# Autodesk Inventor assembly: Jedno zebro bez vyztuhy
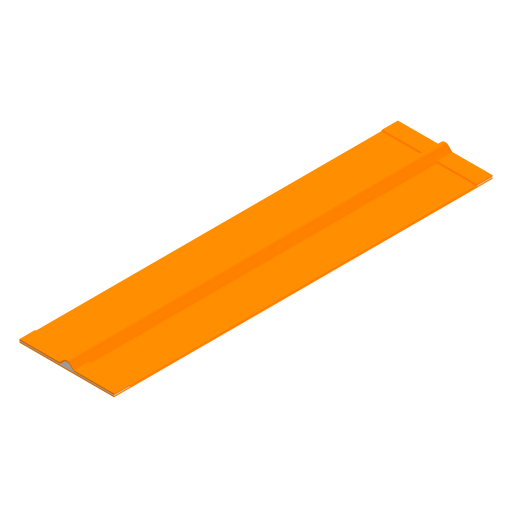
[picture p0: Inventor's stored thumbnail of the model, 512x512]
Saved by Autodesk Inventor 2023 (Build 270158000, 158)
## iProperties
Created: 2025-03
Part Number: Jedno zebro bez vyztuhy
Document SubType Name: Assembly
Designer: tomik
Author: tomik
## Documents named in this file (4)
- C:\Users\tomik\Desktop\Růčka_Tomáš_přílohy\Vyztužení\Jedno žebro\Jedno zebro bez vyztuhy.iam
- C:\Users\tomik\Desktop\Diplomka\Struktury\Desky\Struktury_20.3\Jedno žebro bez výztuhy\Spodni tkanina 50x200.ipt
- C:\Users\tomik\Desktop\Diplomka\Struktury\Desky\Struktury_20.3\Jedno žebro bez výztuhy\Zebro bez vyztuhy.ipt
- C:\Users\tomik\Desktop\Diplomka\Struktury\Desky\Struktury_20.3\Jedno žebro bez výztuhy\Horni tkanina.ipt
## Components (3 placed, 3 different names)
1. Spodni tkanina 50x200:1 — Proti sobě:1, Proti sobě:2, Stejný směr:1, Proti sobě:3, Stejný směr:2, Proti sobě:4, Proti sobě:5
2. Zebro bez vyztuhy:1 — Proti sobě:3, Stejný směr:2, Proti sobě:4, Proti sobě:6, Proti sobě:7
3. Horni tkanina:1 — Proti sobě:5, Proti sobě:6, Proti sobě:7, Stejný směr:3
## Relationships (10: Mate 7, Flush 3)
- Proti sobě:1 [Mate]: Spodni tkanina 50x200:1
- Proti sobě:2 [Mate]: Spodni tkanina 50x200:1
- Stejný směr:1 [Flush]: Spodni tkanina 50x200:1
- Proti sobě:3 [Mate]: Spodni tkanina 50x200:1 ↔ Zebro bez vyztuhy:1
- Stejný směr:2 [Flush]: Spodni tkanina 50x200:1 ↔ Zebro bez vyztuhy:1
- Proti sobě:4 [Mate]: Spodni tkanina 50x200:1 ↔ Zebro bez vyztuhy:1
- Proti sobě:5 [Mate]: Spodni tkanina 50x200:1 ↔ Horni tkanina:1
- Proti sobě:6 [Mate]: Zebro bez vyztuhy:1 ↔ Horni tkanina:1
- Proti sobě:7 [Mate]: Zebro bez vyztuhy:1 ↔ Horni tkanina:1
- Stejný směr:3 [Flush]: Horni tkanina:1
